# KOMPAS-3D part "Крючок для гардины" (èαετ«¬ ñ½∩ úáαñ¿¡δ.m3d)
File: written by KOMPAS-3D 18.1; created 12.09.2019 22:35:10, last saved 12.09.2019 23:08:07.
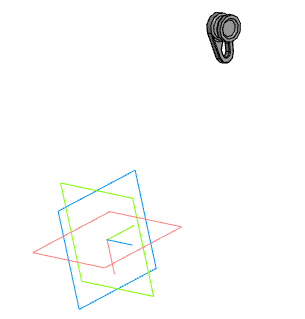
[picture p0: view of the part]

Document properties: Автор: 1; Полное имя файла: D:\Документы\Чертежи\3д модели\Крючок для гардины.m3d

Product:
- Part/product: Крючок для гардины
    Масса: 0.00765116

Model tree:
1. Эскиз:1
2. Элемент выдавливания:1
     Расстояние 1 = 4
3. Эскиз:2  (with: Элемент выдавливания:1)
4. Элемент выдавливания:2
     Расстояние 1 = 2.6
5. Эскиз:3  (with: Элемент выдавливания:2)
6. Элемент выдавливания:3
     Расстояние 1 = 3
7. Эскиз:4  (with: Элемент выдавливания:1, Элемент выдавливания:2)
8. Элемент выдавливания:4
     Расстояние 2 = 1
9. Скругление:1  (with: Элемент выдавливания:1)
     Радиус = 1
10. Скругление:2  (with: Элемент выдавливания:3, Элемент выдавливания:2)
     Радиус = 0.4
11. Скругление:3  (with: Элемент выдавливания:4)
     Радиус = 1
12. Скругление:4  (with: Элемент выдавливания:1, Элемент выдавливания:4)
     Радиус = 0.4
13. Скругление:5  (with: Скругление:3)
     Радиус = 0.4
14. Эскиз:5  (with: Элемент выдавливания:3)
15. Элемент выдавливания:5
     Расстояние 2 = 1
16. Скругление:6  (with: Элемент выдавливания:5)
     Радиус = 1
17. Эскиз:6  (with: Элемент выдавливания:1, Скругление:4)
18. Элемент выдавливания:6
     Расстояние 2 = 2
19. Скругление:7  (with: Элемент выдавливания:6)
     Радиус = 2
20. Скругление:8  (with: Элемент выдавливания:6)
     Радиус = 0.4
21. Скругление:9  (with: Элемент выдавливания:3)
     Радиус = 1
